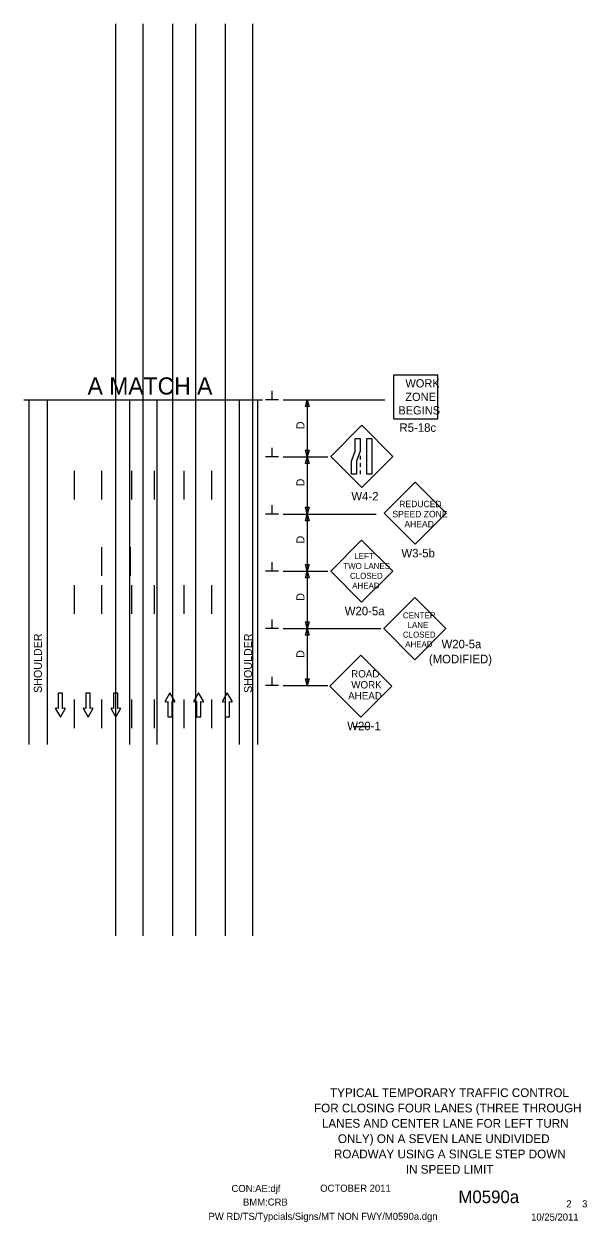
# Model space of a CAD drawing. Extents: x 16730 to 19504, y 5662 to 6979.
# Drawn here: x 17938 to 18431, y 5932 to 6979 of the extents above; entities that cross this region are included whole.
import ezdxf

# ---------------------------------------------------------------- set-up
doc = ezdxf.new("R2010")
doc.units = 0
for name, color, linetype in [('ALI_LEGAL_EX', 7, 'Continuous'), ('BORDER', 7, 'Continuous'), ('BORDER_SIGNAL_WO', 7, 'Continuous'), ('MT_SCRATCH_LEVEL_E', 7, 'Continuous'), ('PAVT_EDGE_EX', 7, 'Continuous'), ('TRAFFIC_SIGNS_PR', 7, 'Continuous'), ('TYPICAL_TEXT_DIMEN_PR', 7, 'Continuous')]:
    doc.layers.add(name, color=color, linetype=linetype)

msp = doc.modelspace()

# ---------------------------------------------------------------- linework, layer by layer
at = {"layer": 'ALI_LEGAL_EX'}
for p, q in [((18018.4, 6182.2), (18018.4, 6979.4)), ((18018.4, 6182.2), (18018.4, 6979.4)), ((18042.4, 6182.2), (18042.4, 6979.4)), ((18042.4, 6182.2), (18042.4, 6979.4)), ((18068.4, 6182.2), (18068.4, 6979.4)), ((18068.4, 6182.2), (18068.4, 6979.4)), ((18088.4, 6182.2), (18088.4, 6979.4)), ((18088.4, 6182.2), (18088.4, 6979.4)), ((18114.4, 6182.2), (18114.4, 6979.4)), ((18114.4, 6182.2), (18114.4, 6979.4)), ((18138.4, 6182.2), (18138.4, 6979.4)), ((18138.4, 6182.2), (18138.4, 6979.4))]:
    msp.add_line(p, q, dxfattribs=at)
for points in [[(17982.4, 6563.7), (17982.4, 6588.7)], [(18006.4, 6563.7), (18006.4, 6588.7)], [(18032.4, 6563.7), (18032.4, 6588.7)], [(18052.4, 6563.7), (18052.4, 6588.7)], [(18078.4, 6563.7), (18078.4, 6588.7)], [(18102.4, 6563.7), (18102.4, 6588.7)], [(17982.4, 6463.7), (17982.4, 6488.7)], [(18006.4, 6463.7), (18006.4, 6488.7)], [(18032.4, 6463.7), (18032.4, 6488.7)], [(18052.4, 6463.7), (18052.4, 6488.7)], [(18078.4, 6463.7), (18078.4, 6488.7)], [(18102.4, 6463.7), (18102.4, 6488.7)], [(17982.4, 6363.7), (17982.4, 6388.7)], [(18006.4, 6363.7), (18006.4, 6388.7)], [(18032.4, 6363.7), (18032.4, 6388.7)], [(18052.4, 6363.7), (18052.4, 6388.7)], [(18078.4, 6363.7), (18078.4, 6388.7)], [(18102.4, 6363.7), (18102.4, 6388.7)]]:
    msp.add_lwpolyline(points, dxfattribs=at)
at = {"layer": 'MT_SCRATCH_LEVEL_E'}
for p, q in [((17971.8, 6394.2), (17968.1, 6394.2)), ((17968.1, 6394.2), (17968.1, 6380.9)), ((17971.8, 6394.2), (17968.1, 6394.2)), ((17968.1, 6394.2), (17968.1, 6380.9)), ((17971.8, 6380.9), (17971.8, 6394.2)), ((17971.8, 6380.9), (17971.8, 6394.2)), ((17996.1, 6394.2), (17992.3, 6394.2)), ((17992.3, 6394.2), (17992.3, 6380.9)), ((17996.1, 6394.2), (17992.3, 6394.2)), ((17992.3, 6394.2), (17992.3, 6380.9)), ((17996.1, 6380.9), (17996.1, 6394.2)), ((17996.1, 6380.9), (17996.1, 6394.2)), ((18020.3, 6394.2), (18016.6, 6394.2)), ((18016.6, 6394.2), (18016.6, 6380.9)), ((18020.3, 6394.2), (18016.6, 6394.2)), ((18016.6, 6394.2), (18016.6, 6380.9)), ((18020.3, 6380.9), (18020.3, 6394.2)), ((18020.3, 6380.9), (18020.3, 6394.2)), ((18065.9, 6394.6), (18061.7, 6387.4)), ((18065.9, 6394.6), (18061.7, 6387.4)), ((18070, 6387.4), (18065.9, 6394.6)), ((18070, 6387.4), (18065.9, 6394.6)), ((18090.9, 6394.6), (18086.8, 6387.4)), ((18090.9, 6394.6), (18086.8, 6387.4)), ((18095.1, 6387.4), (18090.9, 6394.6)), ((18095.1, 6387.4), (18090.9, 6394.6)), ((18116, 6394.6), (18111.9, 6387.4)), ((18116, 6394.6), (18111.9, 6387.4)), ((18120.2, 6387.4), (18116, 6394.6)), ((18120.2, 6387.4), (18116, 6394.6)), ((17965.8, 6380.5), (17970, 6373.3)), ((17965.8, 6380.5), (17970, 6373.3)), ((17968.1, 6380.9), (17966.3, 6381.2)), ((17968.1, 6380.9), (17966.3, 6381.2)), ((17970, 6373.3), (17974.1, 6380.5)), ((17970, 6373.3), (17974.1, 6380.5)), ((17973.6, 6381.2), (17971.8, 6380.9)), ((17973.6, 6381.2), (17971.8, 6380.9)), ((17990.1, 6380.5), (17994.2, 6373.3)), ((17990.1, 6380.5), (17994.2, 6373.3)), ((17992.3, 6380.9), (17990.6, 6381.2)), ((17992.3, 6380.9), (17990.6, 6381.2)), ((17994.2, 6373.3), (17998.3, 6380.5)), ((17994.2, 6373.3), (17998.3, 6380.5)), ((17997.9, 6381.2), (17996.1, 6380.9)), ((17997.9, 6381.2), (17996.1, 6380.9)), ((18014.3, 6380.5), (18018.5, 6373.3)), ((18014.3, 6380.5), (18018.5, 6373.3)), ((18016.6, 6380.9), (18014.8, 6381.2)), ((18016.6, 6380.9), (18014.8, 6381.2)), ((18018.5, 6373.3), (18022.6, 6380.5)), ((18018.5, 6373.3), (18022.6, 6380.5)), ((18022.1, 6381.2), (18020.3, 6380.9)), ((18022.1, 6381.2), (18020.3, 6380.9)), ((18062.2, 6386.7), (18064, 6387)), ((18062.2, 6386.7), (18064, 6387)), ((18064, 6387), (18064, 6373.7)), ((18064, 6387), (18064, 6373.7)), ((18067.7, 6373.7), (18067.7, 6387)), ((18067.7, 6387), (18069.5, 6386.7)), ((18067.7, 6373.7), (18067.7, 6387)), ((18067.7, 6387), (18069.5, 6386.7)), ((18087.3, 6386.7), (18089.1, 6387)), ((18087.3, 6386.7), (18089.1, 6387)), ((18089.1, 6387), (18089.1, 6373.7)), ((18089.1, 6387), (18089.1, 6373.7)), ((18092.8, 6373.7), (18092.8, 6387)), ((18092.8, 6387), (18094.6, 6386.7)), ((18092.8, 6373.7), (18092.8, 6387)), ((18092.8, 6387), (18094.6, 6386.7)), ((18112.4, 6386.7), (18114.2, 6387)), ((18112.4, 6386.7), (18114.2, 6387)), ((18114.2, 6387), (18114.2, 6373.7)), ((18114.2, 6387), (18114.2, 6373.7)), ((18117.9, 6373.7), (18117.9, 6387)), ((18117.9, 6387), (18119.7, 6386.7)), ((18117.9, 6373.7), (18117.9, 6387)), ((18117.9, 6387), (18119.7, 6386.7)), ((18064, 6373.7), (18067.7, 6373.7)), ((18064, 6373.7), (18067.7, 6373.7)), ((18089.1, 6373.7), (18092.8, 6373.7)), ((18089.1, 6373.7), (18092.8, 6373.7)), ((18114.2, 6373.7), (18117.9, 6373.7)), ((18114.2, 6373.7), (18117.9, 6373.7))]:
    msp.add_line(p, q, dxfattribs=at)
for centre, start, end in [((17966.2, 6380.7), 80.0362, 209.7731), ((17966.2, 6380.7), 80.0362, 209.7731), ((17973.7, 6380.7), 330.4248, 99.9638), ((17973.7, 6380.7), 330.4248, 99.9638), ((17990.5, 6380.7), 80.0362, 209.7731), ((17990.5, 6380.7), 80.0362, 209.7731), ((17997.9, 6380.7), 330.4248, 99.9638), ((17997.9, 6380.7), 330.4248, 99.9638), ((18014.8, 6380.7), 80.0362, 209.7731), ((18014.8, 6380.7), 80.0362, 209.7731), ((18022.2, 6380.7), 330.4248, 99.9638), ((18022.2, 6380.7), 330.4248, 99.9638), ((18062.1, 6387.1), 150.4248, 279.9638), ((18062.1, 6387.1), 150.4248, 279.9638), ((18069.6, 6387.1), 260.0362, 29.7731), ((18069.6, 6387.1), 260.0362, 29.7731), ((18087.2, 6387.1), 150.4248, 279.9638), ((18087.2, 6387.1), 150.4248, 279.9638), ((18094.7, 6387.1), 260.0362, 29.7731), ((18094.7, 6387.1), 260.0362, 29.7731), ((18112.3, 6387.1), 150.4248, 279.9638), ((18112.3, 6387.1), 150.4248, 279.9638), ((18119.8, 6387.1), 260.0362, 29.7731), ((18119.8, 6387.1), 260.0362, 29.7731)]:
    msp.add_arc(centre, 0.463, start, end, dxfattribs=at)
at = {"layer": 'PAVT_EDGE_EX'}
for p, q in [((17942.4, 6650.9), (17942.4, 6349.5)), ((17958.4, 6650.9), (17958.4, 6349.5)), ((18030.4, 6650.9), (18030.4, 6349.5)), ((18054.4, 6650.9), (18054.4, 6349.5)), ((18126.4, 6650.9), (18126.4, 6349.5)), ((18142.4, 6650.9), (18142.4, 6349.5))]:
    msp.add_line(p, q, dxfattribs=at)
for points in [[(18006.4, 6496.9), (18006.4, 6521.9)], [(18031.4, 6496.9), (18031.4, 6521.9)]]:
    msp.add_lwpolyline(points, dxfattribs=at)
at = {"layer": 'TRAFFIC_SIGNS_PR'}
for p, q in [((18261.9, 6634.3), (18261.9, 6672.7)), ((18261.9, 6672.7), (18300.3, 6672.7)), ((18300.3, 6634.3), (18300.3, 6672.7)), ((18261.9, 6634.3), (18300.3, 6634.3)), ((18233.7, 6628.5), (18206.5, 6601.3)), ((18260.8, 6601.3), (18233.7, 6628.5)), ((18206.5, 6601.3), (18233.7, 6574.2)), ((18232.4, 6601.8), (18232.4, 6598.6)), ((18233.7, 6574.2), (18260.8, 6601.3)), ((18232.4, 6595.4), (18232.4, 6592.2)), ((18232.4, 6589), (18232.4, 6585.8)), ((18280.4, 6578.8), (18253.3, 6551.6)), ((18307.6, 6551.6), (18280.4, 6578.8)), ((18253.3, 6551.6), (18280.4, 6524.5)), ((18280.4, 6524.5), (18307.6, 6551.6)), ((18233.6, 6528.1), (18206.5, 6501)), ((18260.8, 6501), (18233.6, 6528.1)), ((18206.5, 6501), (18233.6, 6473.8)), ((18233.6, 6473.8), (18260.8, 6501)), ((18280.1, 6477.8), (18252.9, 6450.7)), ((18307.3, 6450.7), (18280.1, 6477.8)), ((18252.9, 6450.7), (18280.1, 6423.5)), ((18280.1, 6423.5), (18307.3, 6450.7)), ((18232.8, 6427.6), (18205.7, 6400.4)), ((18260, 6400.4), (18232.8, 6427.6)), ((18205.7, 6400.4), (18232.8, 6373.3)), ((18232.8, 6373.3), (18260, 6400.4))]:
    msp.add_line(p, q, dxfattribs=at)
for points in [[(18232.4, 6617.1), (18232.4, 6605.9), (18229.1, 6597), (18229.1, 6585.8), (18224.6, 6585.8), (18224.6, 6597), (18227.9, 6605.9), (18227.9, 6617.1)], [(18242.5, 6617.1), (18242.5, 6585.8), (18238.1, 6585.8), (18238.1, 6617.1)]]:
    msp.add_lwpolyline(points, close=True, dxfattribs=at)
at = {"layer": 'TYPICAL_TEXT_DIMEN_PR'}
for p, q in [((18155.2, 6650.9), (18155.2, 6658.7)), ((17938.1, 6650.9), (18146.7, 6650.9)), ((18030.4, 6650.9), (18054.4, 6650.9)), ((18160.8, 6650.9), (18149.5, 6650.9)), ((18165, 6650.9), (18253.8, 6650.9)), ((18184.5, 6645), (18186, 6650.9)), ((18186, 6645), (18184.5, 6645)), ((18186, 6650.9), (18186, 6600.9)), ((18186, 6650.9), (18187.6, 6645)), ((18187.6, 6645), (18186, 6645)), ((18160.8, 6600.9), (18149.5, 6600.9)), ((18155.2, 6600.9), (18155.2, 6608.7)), ((18165, 6600.9), (18204, 6600.9)), ((18186, 6600.9), (18184.5, 6606.8)), ((18184.5, 6606.8), (18186, 6606.8)), ((18184.5, 6595), (18186, 6600.9)), ((18186, 6606.8), (18187.6, 6606.8)), ((18187.6, 6606.8), (18186, 6600.9)), ((18186, 6600.9), (18186, 6550.9)), ((18186, 6600.9), (18187.6, 6595)), ((18186, 6595), (18184.5, 6595)), ((18187.6, 6595), (18186, 6595)), ((18155.2, 6550.9), (18155.2, 6558.7)), ((18160.8, 6550.9), (18149.5, 6550.9)), ((18165, 6550.9), (18246.4, 6550.9)), ((18186, 6550.9), (18184.5, 6556.8)), ((18184.5, 6556.8), (18186, 6556.8)), ((18184.5, 6545), (18186, 6550.9)), ((18186, 6556.8), (18187.6, 6556.8)), ((18187.6, 6556.8), (18186, 6550.9)), ((18186, 6550.9), (18186, 6500.9)), ((18186, 6550.9), (18187.6, 6545)), ((18186, 6545), (18184.5, 6545)), ((18187.6, 6545), (18186, 6545)), ((18155.2, 6500.9), (18155.2, 6508.7)), ((18186, 6500.9), (18184.5, 6506.8)), ((18184.5, 6506.8), (18186, 6506.8)), ((18186, 6506.8), (18187.6, 6506.8)), ((18187.6, 6506.8), (18186, 6500.9)), ((18160.8, 6500.9), (18149.5, 6500.9)), ((18165, 6500.9), (18204, 6500.9)), ((18184.5, 6495), (18186, 6500.9)), ((18186, 6500.9), (18186, 6450.9)), ((18186, 6500.9), (18187.6, 6495)), ((18186, 6495), (18184.5, 6495)), ((18187.6, 6495), (18186, 6495)), ((18155.2, 6450.9), (18155.2, 6458.7)), ((18186, 6450.9), (18184.5, 6456.8)), ((18184.5, 6456.8), (18186, 6456.8)), ((18186, 6456.8), (18187.6, 6456.8)), ((18187.6, 6456.8), (18186, 6450.9)), ((18160.8, 6450.9), (18149.5, 6450.9)), ((18165, 6450.9), (18250.5, 6450.9)), ((18184.5, 6445), (18186, 6450.9)), ((18186, 6445), (18184.5, 6445)), ((18186, 6450.9), (18186, 6400.9)), ((18186, 6450.9), (18187.6, 6445)), ((18187.6, 6445), (18186, 6445)), ((18160.8, 6400.9), (18149.5, 6400.9)), ((18155.2, 6400.9), (18155.2, 6408.7)), ((18165, 6400.9), (18204, 6400.9)), ((18186, 6400.9), (18184.5, 6406.8)), ((18184.5, 6406.8), (18186, 6406.8)), ((18186, 6406.8), (18187.6, 6406.8)), ((18187.6, 6406.8), (18186, 6400.9)), ((18226.1, 6365.1), (18240.4, 6365.1))]:
    msp.add_line(p, q, dxfattribs=at)

# ---------------------------------------------------------------- texts
at = {"layer": 'BORDER'}
for s, p in [('TYPICAL TEMPORARY TRAFFIC CONTROL', (18205.9, 6041.1)), ('FOR CLOSING FOUR LANES (THREE THROUGH', (18191.9, 6027.7)), ('LANES AND CENTER LANE FOR LEFT TURN', (18198.8, 6014.3)), ('ONLY) ON A SEVEN LANE UNDIVIDED', (18212.8, 6000.9)), ('ROADWAY USING A SINGLE STEP DOWN', (18209.3, 5987.5)), ('IN SPEED LIMIT', (18272.2, 5974.1))]:
    msp.add_text(s, height=7.647, dxfattribs=at).set_placement(p)
at = {"layer": 'BORDER_SIGNAL_WO'}
for s, height, p in [('CON:AE:djf', 6.2, (18119.7, 5958.1)), ('    OCTOBER 2011    ', 6.2, (18188.1, 5958.3)), ('BMM:CRB   ', 6.2, (18129.8, 5946.2)), ('    M0590a   ', 11, (18301.9, 5948.4)), (' 2    3 ', 6.2, (18410.4, 5944.7)), ('PW RD/TS/Typcials/Signs/MT NON FWY/M0590a.dgn    ', 6.2, (18099.6, 5933.7)), ('10/25/2011    ', 6.2, (18381.9, 5933.1))]:
    msp.add_text(s, height=height, dxfattribs=at).set_placement(p)
at = {"layer": 'TRAFFIC_SIGNS_PR'}
for s, height, p in [('WORK', 7.22, (18271.9, 6661.6)), ('ZONE', 7.22, (18271.8, 6649.8)), ('BEGINS', 7.22, (18265.7, 6638)), ('R5-18c', 7.44, (18266.7, 6622.8)), ('W4-2', 7.44, (18224.6, 6562.8)), ('REDUCED', 5.6, (18266.5, 6556.9)), ('SPEED ZONE', 5.6, (18260.5, 6548.1)), ('AHEAD', 5.6, (18271, 6539.3)), ('LEFT', 5.2, (18227.2, 6511.5)), ('W3-5b', 7.44, (18268.4, 6513)), ('TWO LANES', 5.2, (18217.5, 6502.9)), ('CLOSED', 5.2, (18223.4, 6494.3)), ('AHEAD', 5.2, (18225.3, 6485.7)), ('W20-5a', 7.44, (18218.8, 6462.4)), ('CENTER', 5.2, (18269.7, 6459.7)), ('LANE', 5.2, (18273.8, 6451.3)), ('CLOSED', 5.2, (18269.7, 6442.9)), ('AHEAD', 5.2, (18271.7, 6434.5)), ('W20-5a', 7.44, (18303.5, 6433.5)), ('(MODIFIED)', 7.44, (18292.4, 6420.4)), ('ROAD', 6.4, (18224.4, 6408)), ('WORK', 6.4, (18224.5, 6398.4)), ('AHEAD', 6.4, (18221.8, 6388.8)), ('W20-1', 7.44, (18221, 6361.9))]:
    msp.add_text(s, height=height, dxfattribs=at).set_placement(p)
at = {"layer": 'TYPICAL_TEXT_DIMEN_PR'}
msp.add_text('A MATCH A', height=15, dxfattribs=at).set_placement((17993.8, 6655.4))
for s, p in [('D', (18183.5, 6625.1)), ('D', (18183.5, 6575.1)), ('D', (18183.5, 6525.1)), ('D', (18183.5, 6475.1)), ('SHOULDER', (17953.8, 6394.5)), ('SHOULDER', (18137.7, 6394.5)), ('D', (18183.5, 6425.1))]:
    msp.add_text(s, height=7, rotation=90, dxfattribs=at).set_placement(p)

doc.saveas('drawing.dxf')
